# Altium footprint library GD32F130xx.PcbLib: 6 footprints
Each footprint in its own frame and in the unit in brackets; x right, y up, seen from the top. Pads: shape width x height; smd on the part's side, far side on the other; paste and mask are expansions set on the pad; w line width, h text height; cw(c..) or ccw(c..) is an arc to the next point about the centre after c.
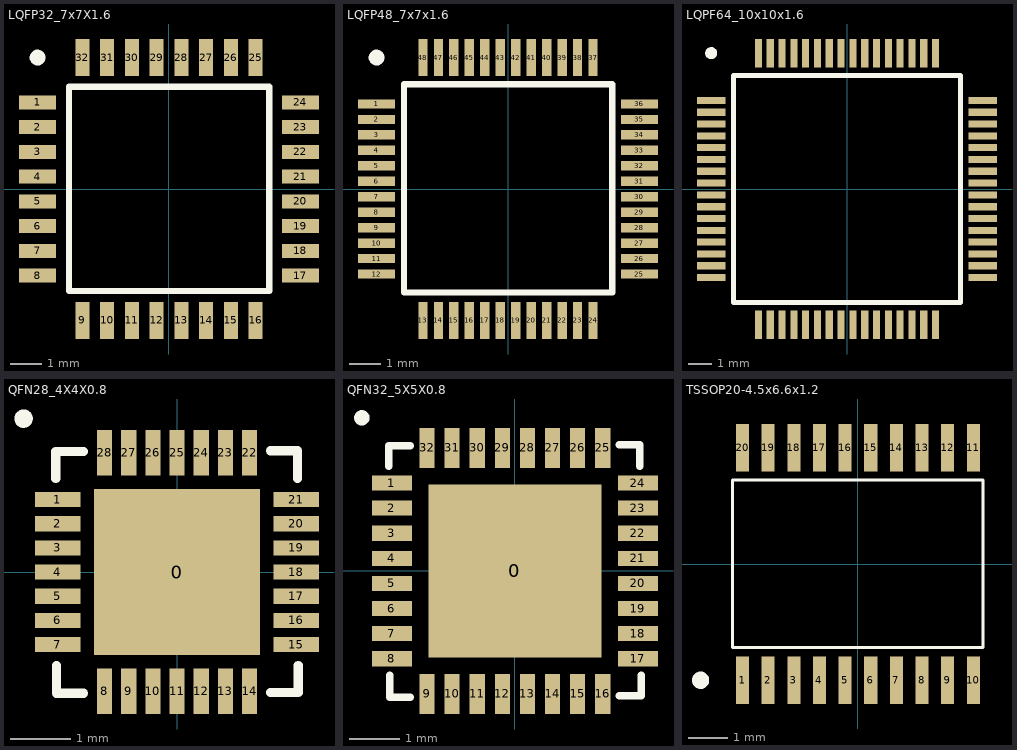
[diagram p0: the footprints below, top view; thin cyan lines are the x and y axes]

## LQFP32_7x7X1.6 [mm]
pads (32):
  rect 1.2x0.45 smd: 1(-4.25,2.8) 2(-4.25,2) 3(-4.25,1.2) 4(-4.25,0.4) 5(-4.25,-0.4) 6(-4.25,-1.2) 7(-4.25,-2) 8(-4.25,-2.8) 17(4.25,-2.8) 18(4.25,-2) 19(4.25,-1.2) 20(4.25,-0.4) 21(4.25,0.4) 22(4.25,1.2) 23(4.25,2) 24(4.25,2.8)
  rect 0.45x1.2 smd: 9(-2.8,-4.25) 10(-2,-4.25) 11(-1.2,-4.25) 12(-0.4,-4.25) 13(0.4,-4.25) 14(1.2,-4.25) 15(2,-4.25) 16(2.8,-4.25) 25(2.8,4.25) 26(2,4.25) 27(1.2,4.25) 28(0.4,4.25) 29(-0.4,4.25) 30(-1.2,4.25) 31(-2,4.25) 32(-2.8,4.25)
Top Overlay:
  circle w0.254: c-4.25,4.25 r0.127
  lines w0.203: -3.234,-3.296 3.243,-3.296 3.243,3.308 -3.234,3.308 -3.234,-3.296
3D body "TQFP80P900X900X160-32N.step": height 1.6, standoff 0, extent -4.5,-4.5 4.5,4.5

## LQFP48_7x7x1.6 [mm]
pads (48):
  rect 1.2x0.3 smd: 1(-4.25,2.75) 2(-4.25,2.25) 3(-4.25,1.75) 4(-4.25,1.25) 5(-4.25,0.75) 6(-4.25,0.25) 7(-4.25,-0.25) 8(-4.25,-0.75) 9(-4.25,-1.25) 10(-4.25,-1.75) 11(-4.25,-2.25) 12(-4.25,-2.75) 25(4.25,-2.75) 26(4.25,-2.25) 27(4.25,-1.75) 28(4.25,-1.25) 29(4.25,-0.75) 30(4.25,-0.25) 31(4.25,0.25) 32(4.25,0.75) 33(4.25,1.25) 34(4.25,1.75) 35(4.25,2.25) 36(4.25,2.75)
  rect 0.3x1.2 smd: 13(-2.75,-4.25) 14(-2.25,-4.25) 15(-1.75,-4.25) 16(-1.25,-4.25) 17(-0.75,-4.25) 18(-0.25,-4.25) 19(0.25,-4.25) 20(0.75,-4.25) 21(1.25,-4.25) 22(1.75,-4.25) 23(2.25,-4.25) 24(2.75,-4.25) 37(2.75,4.25) 38(2.25,4.25) 39(1.75,4.25) 40(1.25,4.25) 41(0.75,4.25) 42(0.25,4.25) 43(-0.25,4.25) 44(-0.75,4.25) 45(-1.25,4.25) 46(-1.75,4.25) 47(-2.25,4.25) 48(-2.75,4.25)
Top Overlay:
  circle w0.254: c-4.25,4.25 r0.127
  lines w0.203: -3.361,-3.346 3.37,-3.346 3.37,3.385 -3.361,3.385 -3.361,-3.346
3D body "TSQFP50P900X900X160-48N.step": height 1.6, standoff 0, extent -4.5,-4.5 4.5,4.5

## LQPF64_10x10x1.6 [mm]
pads (64):
  rect 1.2x0.3 smd: 1(-5.75,3.75) 2(-5.75,3.25) 3(-5.75,2.75) 4(-5.75,2.25) 5(-5.75,1.75) 6(-5.75,1.25) 7(-5.75,0.75) 8(-5.75,0.25) 9(-5.75,-0.25) 10(-5.75,-0.75) 11(-5.75,-1.25) 12(-5.75,-1.75) 13(-5.75,-2.25) 14(-5.75,-2.75) 15(-5.75,-3.25) 16(-5.75,-3.75) 33(5.75,-3.75) 34(5.75,-3.25) 35(5.75,-2.75) 36(5.75,-2.25) 37(5.75,-1.75) 38(5.75,-1.25) 39(5.75,-0.75) 40(5.75,-0.25) 41(5.75,0.25) 42(5.75,0.75) 43(5.75,1.25) 44(5.75,1.75) 45(5.75,2.25) 46(5.75,2.75) 47(5.75,3.25) 48(5.75,3.75)
  rect 0.3x1.2 smd: 17(-3.75,-5.75) 18(-3.25,-5.75) 19(-2.75,-5.75) 20(-2.25,-5.75) 21(-1.75,-5.75) 22(-1.25,-5.75) 23(-0.75,-5.75) 24(-0.25,-5.75) 25(0.25,-5.75) 26(0.75,-5.75) 27(1.25,-5.75) 28(1.75,-5.75) 29(2.25,-5.75) 30(2.75,-5.75) 31(3.25,-5.75) 32(3.75,-5.75) 49(3.75,5.75) 50(3.25,5.75) 51(2.75,5.75) 52(2.25,5.75) 53(1.75,5.75) 54(1.25,5.75) 55(0.75,5.75) 56(0.25,5.75) 57(-0.25,5.75) 58(-0.75,5.75) 59(-1.25,5.75) 60(-1.75,5.75) 61(-2.25,5.75) 62(-2.75,5.75) 63(-3.25,5.75) 64(-3.75,5.75)
Top Overlay:
  circle w0.254: c-5.75,5.75 r0.127
  lines w0.203: -4.801,-4.801 -4.801,4.801 4.801,4.801 4.801,-4.801 -4.801,-4.801
3D body "TSQFP50P1200X1200X160-64N.step": height 1.6, standoff 0, extent -6,-6 6,6

## QFN28_4X4X0.8 [mm]
pads (29):
  rect 2.75x2.75 smd: 0(0,0)
  rect 0.75x0.25 smd: 1(-1.975,1.2) 2(-1.975,0.8) 3(-1.975,0.4) 4(-1.975,0) 5(-1.975,-0.4) 6(-1.975,-0.8) 7(-1.975,-1.2) 15(1.975,-1.2) 16(1.975,-0.8) 17(1.975,-0.4) 18(1.975,0) 19(1.975,0.4) 20(1.975,0.8) 21(1.975,1.2)
  rect 0.25x0.75 smd: 8(-1.2,-1.975) 9(-0.8,-1.975) 10(-0.4,-1.975) 11(0,-1.975) 12(0.4,-1.975) 13(0.8,-1.975) 14(1.2,-1.975) 22(1.2,1.975) 23(0.8,1.975) 24(0.4,1.975) 25(0,1.975) 26(-0.4,1.975) 27(-0.8,1.975) 28(-1.2,1.975)
Top Overlay:
  circle w0.152: c-2.54,2.54 r0.076
  lines w0.152: -2.007,1.549 -2.007,1.993 -1.549,1.993 ; -1.993,-1.549 -1.993,-2.007 -1.549,-2.007 ; 1.549,-1.993 2.007,-1.993 2.007,-1.549 ; 1.549,2.007 1.993,2.007 1.993,1.549
3D body "QFN40P400X400X80_HS-29N.step": height 0.8, standoff 0, extent -2.051,-2.051 2.051,2.051

## QFN32_5X5X0.8 [mm]
pads (33):
  rect 3.45x3.45 smd: 0(0,0)
  rect 0.8x0.3 smd: 1(-2.45,1.75) 2(-2.45,1.25) 3(-2.45,0.75) 4(-2.45,0.25) 5(-2.45,-0.25) 6(-2.45,-0.75) 7(-2.45,-1.25) 8(-2.45,-1.75) 17(2.45,-1.75) 18(2.45,-1.25) 19(2.45,-0.75) 20(2.45,-0.25) 21(2.45,0.25) 22(2.45,0.75) 23(2.45,1.25) 24(2.45,1.75)
  rect 0.3x0.8 smd: 9(-1.75,-2.45) 10(-1.25,-2.45) 11(-0.75,-2.45) 12(-0.25,-2.45) 13(0.25,-2.45) 14(0.75,-2.45) 15(1.25,-2.45) 16(1.75,-2.45) 25(1.75,2.45) 26(1.25,2.45) 27(0.75,2.45) 28(0.25,2.45) 29(-0.25,2.45) 30(-0.75,2.45) 31(-1.25,2.45) 32(-1.75,2.45)
Top Overlay:
  circle w0.152: c-3.048,3.048 r0.076
  lines w0.152: -2.515,2.083 -2.515,2.489 -2.083,2.489 ; -2.489,-2.083 -2.489,-2.515 -2.083,-2.515 ; 2.083,-2.489 2.515,-2.489 2.515,-2.083 ; 2.083,2.515 2.489,2.515 2.489,2.083
3D body "QFN50P500X500X80_HS-33N.step": height 0.8, standoff 0, extent -2.551,-2.551 2.551,2.551

## TSSOP20-4.5x6.6x1.2 [mm]
pads (20):
  rect 0.33x1.2 smd: 1(-2.925,-2.95) 2(-2.275,-2.95) 3(-1.625,-2.95) 4(-0.975,-2.95) 5(-0.325,-2.95) 6(0.325,-2.95) 7(0.975,-2.95) 8(1.625,-2.95) 9(2.275,-2.95) 10(2.925,-2.95) 11(2.925,2.95) 12(2.275,2.95) 13(1.625,2.95) 14(0.975,2.95) 15(0.325,2.95) 16(-0.325,2.95) 17(-0.975,2.95) 18(-1.625,2.95) 19(-2.275,2.95) 20(-2.925,2.95)
Top Overlay:
  circle w0.254: c-3.988,-2.946 r0.092
  lines w0.076: -3.179,-2.112 3.171,-2.112 3.171,2.13 -3.179,2.13 -3.179,-2.112
3D body "TSOP65P640X120-20N.step": height 1.2, standoff 0, extent -3.3,-3.2 3.3,3.2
